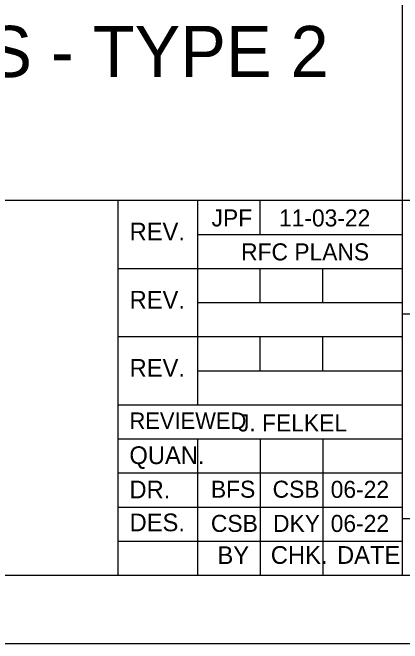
# Model space of a CAD drawing. Extents: x -125.5 to -89.4, y -5.1 to 16.9.
# Drawn here: x -98.306 to -95.45, y -5.066 to -0.44 of the extents above; entities that cross this region are included whole.
import ezdxf

# ---------------------------------------------------------------- set-up
doc = ezdxf.new("R2010")
doc.units = 0
for name, color, linetype in [('BR_BORDER LINES', 7, 'Continuous'), ('BR_TEXT', 7, 'Continuous'), ('Level 31', 7, 'Continuous')]:
    doc.layers.add(name, color=color, linetype=linetype)

msp = doc.modelspace()

# ---------------------------------------------------------------- linework, layer by layer
at = {"layer": 'BR_BORDER LINES'}
for p, q in [((-95.4503, -4.5662), (-95.4503, 0.7104)), ((-102.8989, -1.8161), (-97.5337, -1.8161)), ((-97.5337, -4.5662), (-97.5337, -1.8161)), ((-97.5337, -1.8161), (-90.0334, -1.8161)), ((-96.9503, -1.8161), (-96.9503, -3.3161)), ((-96.492, -2.0661), (-96.492, -1.8161)), ((-96.9503, -2.0661), (-95.4503, -2.0661)), ((-97.5337, -2.3161), (-95.4503, -2.3161)), ((-96.492, -2.5661), (-96.492, -2.3161)), ((-96.0336, -2.5661), (-96.0336, -2.3161)), ((-96.9503, -2.5661), (-95.4503, -2.5661)), ((-95.4503, -2.6494), (-95.4503, -2.6494)), ((-95.4503, -2.6495), (-90.0332, -2.6495)), ((-97.5337, -2.8161), (-95.4503, -2.8161)), ((-96.492, -3.0661), (-96.492, -2.8161)), ((-96.0336, -3.0661), (-96.0336, -2.8161)), ((-96.9503, -3.0661), (-95.4503, -3.0661)), ((-97.5337, -3.3161), (-95.4503, -3.3161)), ((-97.5337, -3.5661), (-95.4503, -3.5661)), ((-96.9503, -3.5661), (-96.9503, -4.5662)), ((-96.492, -3.5661), (-96.492, -4.5662)), ((-96.0336, -3.5661), (-96.0336, -4.5662)), ((-97.5337, -3.8161), (-95.4503, -3.8161)), ((-97.5337, -4.0662), (-95.4503, -4.0662)), ((-95.4503, -4.1495), (-90.0334, -4.1495)), ((-97.5337, -4.3162), (-95.4503, -4.3162)), ((-123.6994, -4.5662), (-90.0334, -4.5662))]:
    msp.add_line(p, q, dxfattribs=at)
at = {"layer": 'Level 31'}
msp.add_lwpolyline([(-125.5328, 16.9339), (-125.5328, -5.0661), (-89.5328, -5.0661), (-89.5328, 16.9339)], dxfattribs=at)

# ---------------------------------------------------------------- texts
at = {"layer": 'BR_TEXT'}
for s, height, p in [('BEARING PAD DETAILS - TYPE 2', 0.375, (-103.821, -0.9121)), ('JPF', 0.12499, (-96.8483, -2.0082)), ('11-03-22', 0.12499, (-96.3542, -2.0082)), ('REV.', 0.13001, (-97.449, -2.1107)), ('RFC PLANS', 0.12499, (-96.6318, -2.2571)), ('REV.', 0.13001, (-97.449, -2.6107)), ('REV.', 0.13001, (-97.449, -3.1107)), ('REVIEWED', 0.12, (-97.4497, -3.4926)), ('J. FELKEL', 0.12499, (-96.6547, -3.5118)), ('QUAN.', 0.13001, (-97.4503, -3.751)), ('DR.', 0.13001, (-97.4501, -4.0025)), ('BFS', 0.12499, (-96.8531, -3.9979)), ('CSB', 0.12499, (-96.401, -3.9979)), ('06-22', 0.12499, (-95.9754, -3.9989)), ('DES.', 0.13001, (-97.449, -4.2438)), ('CSB', 0.12499, (-96.8531, -4.2484)), ('DKY', 0.12499, (-96.3975, -4.2484)), ('06-22', 0.12499, (-95.9754, -4.2489)), ('BY', 0.13001, (-96.805, -4.4842)), ('CHK.', 0.13001, (-96.4142, -4.4828)), ('DATE', 0.13001, (-95.929, -4.4827))]:
    msp.add_text(s, height=height, dxfattribs=at).set_placement(p)

doc.saveas('drawing.dxf')
